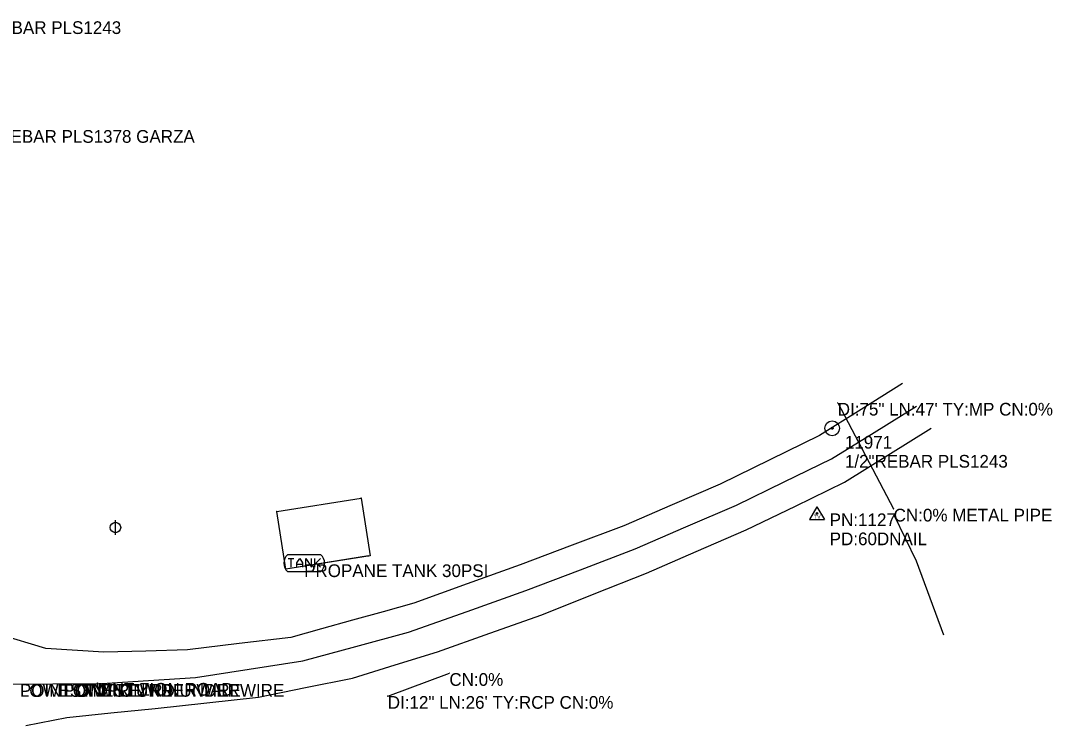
# Model space of a CAD drawing. Extents: x 1050807 to 1053552, y 395828 to 398415.
# Drawn here: x 1052156.1 to 1052561.9, y 397799.4 to 398075.6 of the extents above; entities that cross this region are included whole.
import ezdxf

# ---------------------------------------------------------------- set-up
doc = ezdxf.new("R2010")
doc.units = 0
for name, color, linetype in [('S_BUILDING', 7, 'Continuous'), ('S_CROSS_DRAIN', 7, 'Continuous'), ('S_CROSS_DRAIN_ANNOT', 7, 'Continuous'), ('S_DITCHLINE', 7, 'Continuous'), ('S_DRG_PT_SYM', 7, 'Continuous'), ('S_EDGE_PAVEMENT', 7, 'Continuous'), ('S_ELECTRIC_UTILITIES_ANNOT', 7, 'Continuous'), ('S_IRON_PIN', 7, 'Continuous'), ('S_IRON_PIN_ANNOT', 7, 'Continuous'), ('S_MSC_PT_SYM', 7, 'Continuous'), ('S_PAVEMENT_CROWN', 7, 'Continuous'), ('S_SECONDARY_CTL', 7, 'Continuous'), ('S_SECONDARY_CTL_ANNOT', 7, 'Continuous'), ('S_STR_PT_SYM', 7, 'Continuous'), ('S_SURVEY_TEXT_ANNOT', 7, 'Continuous'), ('S_TANK', 7, 'Continuous'), ('S_TANK_ANNOT', 7, 'Continuous'), ('S_UTILITY_POLE', 7, 'Continuous'), ('S_UTL_PT_SYM', 7, 'Continuous')]:
    doc.layers.add(name, color=color, linetype=linetype)

msp = doc.modelspace()

# ---------------------------------------------------------------- linework, layer by layer
at = {"layer": 'S_BUILDING'}
for p, q in [((1052256.81, 397882.47), (1052290, 397887.72)), ((1052290, 397887.72), (1052293.59, 397865)), ((1052260.4, 397859.75), (1052256.81, 397882.47)), ((1052293.59, 397865), (1052260.4, 397859.75)), ((1052292.98, 397864.9), (1052260.4, 397859.75))]:
    msp.add_line(p, q, dxfattribs=at)
at = {"layer": 'S_CROSS_DRAIN'}
for p, q in [((1052477.48, 397925.17), (1052499.47, 397883.48)), ((1052300.5, 397809.77), (1052324.74, 397818.79))]:
    msp.add_line(p, q, dxfattribs=at)
at = {"layer": 'S_DITCHLINE'}
msp.add_lwpolyline([(1052519.2, 397833.74), (1052513.86, 397848.32), (1052508.52, 397862.91), (1052499.82, 397880.65)], dxfattribs=at)
at = {"layer": 'S_DRG_PT_SYM'}
for points in [[(1052477.48, 397925.17), (1052477.48, 397925.22), (1052477.48, 397925.17), (1052477.43, 397925.17), (1052477.48, 397925.17), (1052477.48, 397925.12), (1052477.48, 397925.17), (1052477.53, 397925.17)], [(1052499.47, 397883.48), (1052499.47, 397883.53), (1052499.47, 397883.48), (1052499.42, 397883.48), (1052499.47, 397883.48), (1052499.47, 397883.43), (1052499.47, 397883.48), (1052499.52, 397883.48)], [(1052324.74, 397818.79), (1052324.74, 397818.84), (1052324.74, 397818.79), (1052324.69, 397818.79), (1052324.74, 397818.79), (1052324.74, 397818.74), (1052324.74, 397818.79), (1052324.79, 397818.79)], [(1052300.5, 397809.77), (1052300.5, 397809.82), (1052300.5, 397809.77), (1052300.45, 397809.77), (1052300.5, 397809.77), (1052300.5, 397809.72), (1052300.5, 397809.77), (1052300.55, 397809.77)]]:
    msp.add_lwpolyline(points, dxfattribs=at)
at = {"layer": 'S_EDGE_PAVEMENT'}
for points in [[(1052502.93, 397932.73), (1052486.63, 397922.5), (1052470.33, 397912.28), (1052450.77, 397902.72), (1052431.22, 397893.16), (1052412.3, 397885), (1052393.38, 397876.83), (1052373, 397869.15), (1052352.62, 397861.47), (1052331.71, 397853.88), (1052310.8, 397846.29), (1052298.69, 397842.94), (1052286.59, 397839.59), (1052274.49, 397836.23), (1052262.39, 397832.88), (1052242.05, 397830.42), (1052221.72, 397827.95), (1052205.29, 397827.5), (1052188.87, 397827.04), (1052166.06, 397828.48), (1052147.64, 397834.05)], [(1052158.09, 397798.17), (1052174.27, 397801.39), (1052191.62, 397803.12), (1052208.97, 397804.85), (1052229.33, 397807.11), (1052249.68, 397809.36), (1052268.14, 397813.11), (1052286.6, 397816.86), (1052303.36, 397822.03), (1052320.12, 397827.19), (1052340.58, 397834.49), (1052361.04, 397841.79), (1052381.62, 397849.97), (1052402.2, 397858.14), (1052421.86, 397866.64), (1052441.51, 397875.15), (1052460.81, 397884.53), (1052480.1, 397893.92), (1052497.16, 397904.54), (1052514.21, 397915.17)]]:
    msp.add_lwpolyline(points, dxfattribs=at)
at = {"layer": 'S_IRON_PIN'}
for radius in [2.91, 0.411, 0.262, 0.212, 0.145, 0.0822, 0.0581]:
    msp.add_circle((1052475.29, 397915.16), radius, dxfattribs=at)
at = {"layer": 'S_MSC_PT_SYM'}
for points in [[(1052172.9, 397814.5), (1052172.9, 397814.55), (1052172.9, 397814.5), (1052172.85, 397814.5), (1052172.9, 397814.5), (1052172.9, 397814.45), (1052172.9, 397814.5), (1052172.95, 397814.5)], [(1052186.39, 397814.92), (1052186.39, 397814.97), (1052186.39, 397814.92), (1052186.34, 397814.92), (1052186.39, 397814.92), (1052186.39, 397814.87), (1052186.39, 397814.92), (1052186.44, 397814.92)]]:
    msp.add_lwpolyline(points, dxfattribs=at)
at = {"layer": 'S_PAVEMENT_CROWN'}
msp.add_lwpolyline([(1052092.01, 397815.11), (1052106.18, 397815), (1052120.36, 397814.9), (1052134.89, 397814.68), (1052149.41, 397814.47), (1052168.73, 397814.57), (1052188.05, 397814.67), (1052206.43, 397815.88), (1052224.82, 397817.09), (1052245.96, 397820.35), (1052267.11, 397823.61), (1052287.9, 397829.23), (1052308.68, 397834.85), (1052331.73, 397843.05), (1052354.77, 397851.25), (1052376.28, 397859.51), (1052397.79, 397867.77), (1052417.71, 397876.32), (1052437.63, 397884.87), (1052456.35, 397894.03), (1052475.08, 397903.2), (1052491.75, 397913.53), (1052508.43, 397923.86)], dxfattribs=at)
at = {"layer": 'S_SECONDARY_CTL'}
for p, q in [((1052469.32, 397884.25), (1052466.31, 397879.29)), ((1052469.32, 397884.25), (1052472.27, 397879.29)), ((1052466.31, 397879.29), (1052472.27, 397879.29))]:
    msp.add_line(p, q, dxfattribs=at)
for radius in [0.311, 0.183, 0.103]:
    msp.add_circle((1052469.32, 397881.64), radius, dxfattribs=at)
at = {"layer": 'S_STR_PT_SYM'}
for points in [[(1052290, 397887.72), (1052290, 397887.77), (1052290, 397887.72), (1052289.95, 397887.72), (1052290, 397887.72), (1052290, 397887.67), (1052290, 397887.72), (1052290.05, 397887.72)], [(1052256.81, 397882.47), (1052256.81, 397882.52), (1052256.81, 397882.47), (1052256.76, 397882.47), (1052256.81, 397882.47), (1052256.81, 397882.42), (1052256.81, 397882.47), (1052256.86, 397882.47)], [(1052292.98, 397864.9), (1052292.98, 397864.95), (1052292.98, 397864.9), (1052292.93, 397864.9), (1052292.98, 397864.9), (1052292.98, 397864.85), (1052292.98, 397864.9), (1052293.03, 397864.9)], [(1052293.59, 397865), (1052293.59, 397865.05), (1052293.59, 397865), (1052293.54, 397865), (1052293.59, 397865), (1052293.59, 397864.95), (1052293.59, 397865), (1052293.64, 397865)], [(1052260.4, 397859.75), (1052260.4, 397859.8), (1052260.4, 397859.75), (1052260.35, 397859.75), (1052260.4, 397859.75), (1052260.4, 397859.7), (1052260.4, 397859.75), (1052260.45, 397859.75)], [(1052260.4, 397859.75), (1052260.4, 397859.8), (1052260.4, 397859.75), (1052260.35, 397859.75), (1052260.4, 397859.75), (1052260.4, 397859.7), (1052260.4, 397859.75), (1052260.45, 397859.75)]]:
    msp.add_lwpolyline(points, dxfattribs=at)
at = {"layer": 'S_TANK'}
for p, q in [((1052261.02, 397865.42), (1052274.13, 397865.42)), ((1052261.28, 397863.93), (1052263.54, 397863.93)), ((1052262.44, 397863.93), (1052262.44, 397860.45)), ((1052264.76, 397862.19), (1052265.93, 397863.93)), ((1052265.93, 397863.93), (1052267.02, 397862.19)), ((1052268.25, 397860.45), (1052268.25, 397863.93)), ((1052268.25, 397863.93), (1052270.51, 397860.45)), ((1052270.51, 397860.45), (1052270.51, 397863.93)), ((1052271.74, 397863.93), (1052271.74, 397860.45)), ((1052271.74, 397861.61), (1052274, 397863.93)), ((1052264.76, 397860.45), (1052264.76, 397862.19)), ((1052267.02, 397861.54), (1052264.76, 397861.54)), ((1052267.02, 397862.19), (1052267.02, 397860.45)), ((1052272.32, 397862.13), (1052274, 397860.45)), ((1052261.02, 397858.77), (1052274.13, 397858.77))]:
    msp.add_line(p, q, dxfattribs=at)
for centre, radius, start, end in [((1052264.2, 397862.09), 4.6, 133.7339, 226.2661), ((1052271.34, 397862.09), 4.34, 309.9965, 50.0035)]:
    msp.add_arc(centre, radius, start, end, dxfattribs=at)
at = {"layer": 'S_UTILITY_POLE'}
msp.add_line((1052193.4, 397873.17), (1052193.4, 397878.96), dxfattribs=at)
msp.add_circle((1052193.4, 397876.1), 2.05, dxfattribs=at)
at = {"layer": 'S_UTL_PT_SYM'}
msp.add_lwpolyline([(1052172.9, 397814.5), (1052172.9, 397814.55), (1052172.9, 397814.5), (1052172.85, 397814.5), (1052172.9, 397814.5), (1052172.9, 397814.45), (1052172.9, 397814.5), (1052172.95, 397814.5)], dxfattribs=at)

# ---------------------------------------------------------------- texts
at = {"layer": 'S_CROSS_DRAIN_ANNOT'}
for s, p in [('DI:75" LN:47\' TY:MP CN:0%', (1052477.48, 397920.17)), ('CN:0% METAL PIPE', (1052499.47, 397878.48)), ('CN:0%', (1052324.74, 397813.79)), ('DI:12" LN:26\' TY:RCP CN:0%', (1052300.5, 397804.77))]:
    msp.add_text(s, height=5, dxfattribs=at).set_placement(p)
at = {"layer": 'S_ELECTRIC_UTILITIES_ANNOT'}
for p in [(1052155.81, 397809.47), (1052172.9, 397809.5)]:
    msp.add_text('LOWEST WIRE', height=5, dxfattribs=at).set_placement(p)
at = {"layer": 'S_IRON_PIN_ANNOT'}
for s, p in [('1/2"REBAR PLS1243', (1052131.59, 398070.35)), ('1/2"REBAR PLS1378 GARZA', (1052135.63, 398027.53)), ('11971', (1052480.29, 397907.16)), ('1/2"REBAR PLS1243', (1052480.29, 397899.66))]:
    msp.add_text(s, height=5, dxfattribs=at).set_placement(p)
at = {"layer": 'S_SECONDARY_CTL'}
msp.add_text('TV', height=1.5, dxfattribs=at).set_placement((1052468.12, 397879.62))
at = {"layer": 'S_SECONDARY_CTL_ANNOT'}
for s, p in [('PN:1127', (1052474.32, 397876.64)), ('PD:60DNAIL', (1052474.32, 397869.14))]:
    msp.add_text(s, height=5, dxfattribs=at).set_placement(p)
at = {"layer": 'S_SURVEY_TEXT_ANNOT'}
for s, p in [('POINT ON RD UNDERWIRE', (1052155.81, 397809.47)), ('POINT ON RD UNDERWIRE', (1052172.9, 397809.5)), ('MNT ZION ROAD', (1052186.39, 397809.92))]:
    msp.add_text(s, height=5, dxfattribs=at).set_placement(p)
at = {"layer": 'S_TANK_ANNOT'}
msp.add_text('PROPANE TANK 30PSI', height=5, dxfattribs=at).set_placement((1052267.6, 397856.61))

doc.saveas('drawing.dxf')
